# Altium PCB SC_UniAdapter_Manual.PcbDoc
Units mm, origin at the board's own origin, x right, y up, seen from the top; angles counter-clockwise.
Board outline 69.5 x 43.5 mm, 2 copper layers (Top Layer, Bottom Layer); 6 components, 60 nets, 150 pads, 27 vias.
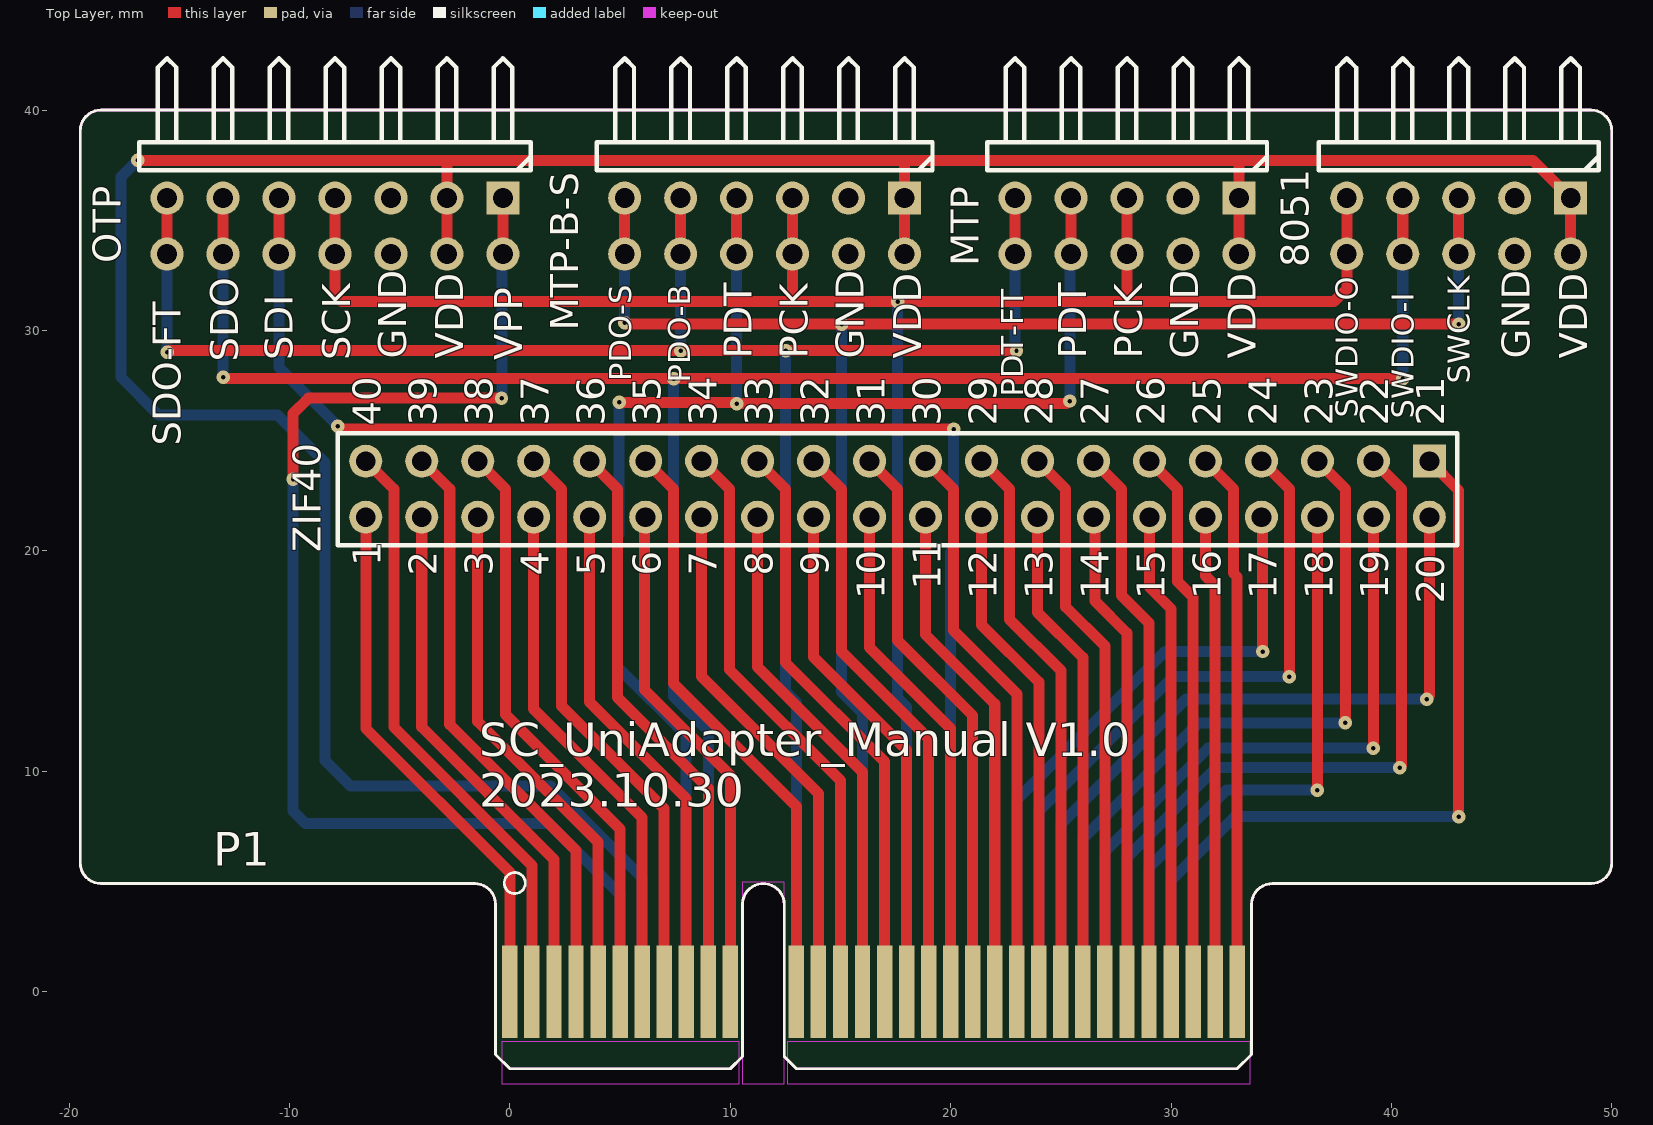
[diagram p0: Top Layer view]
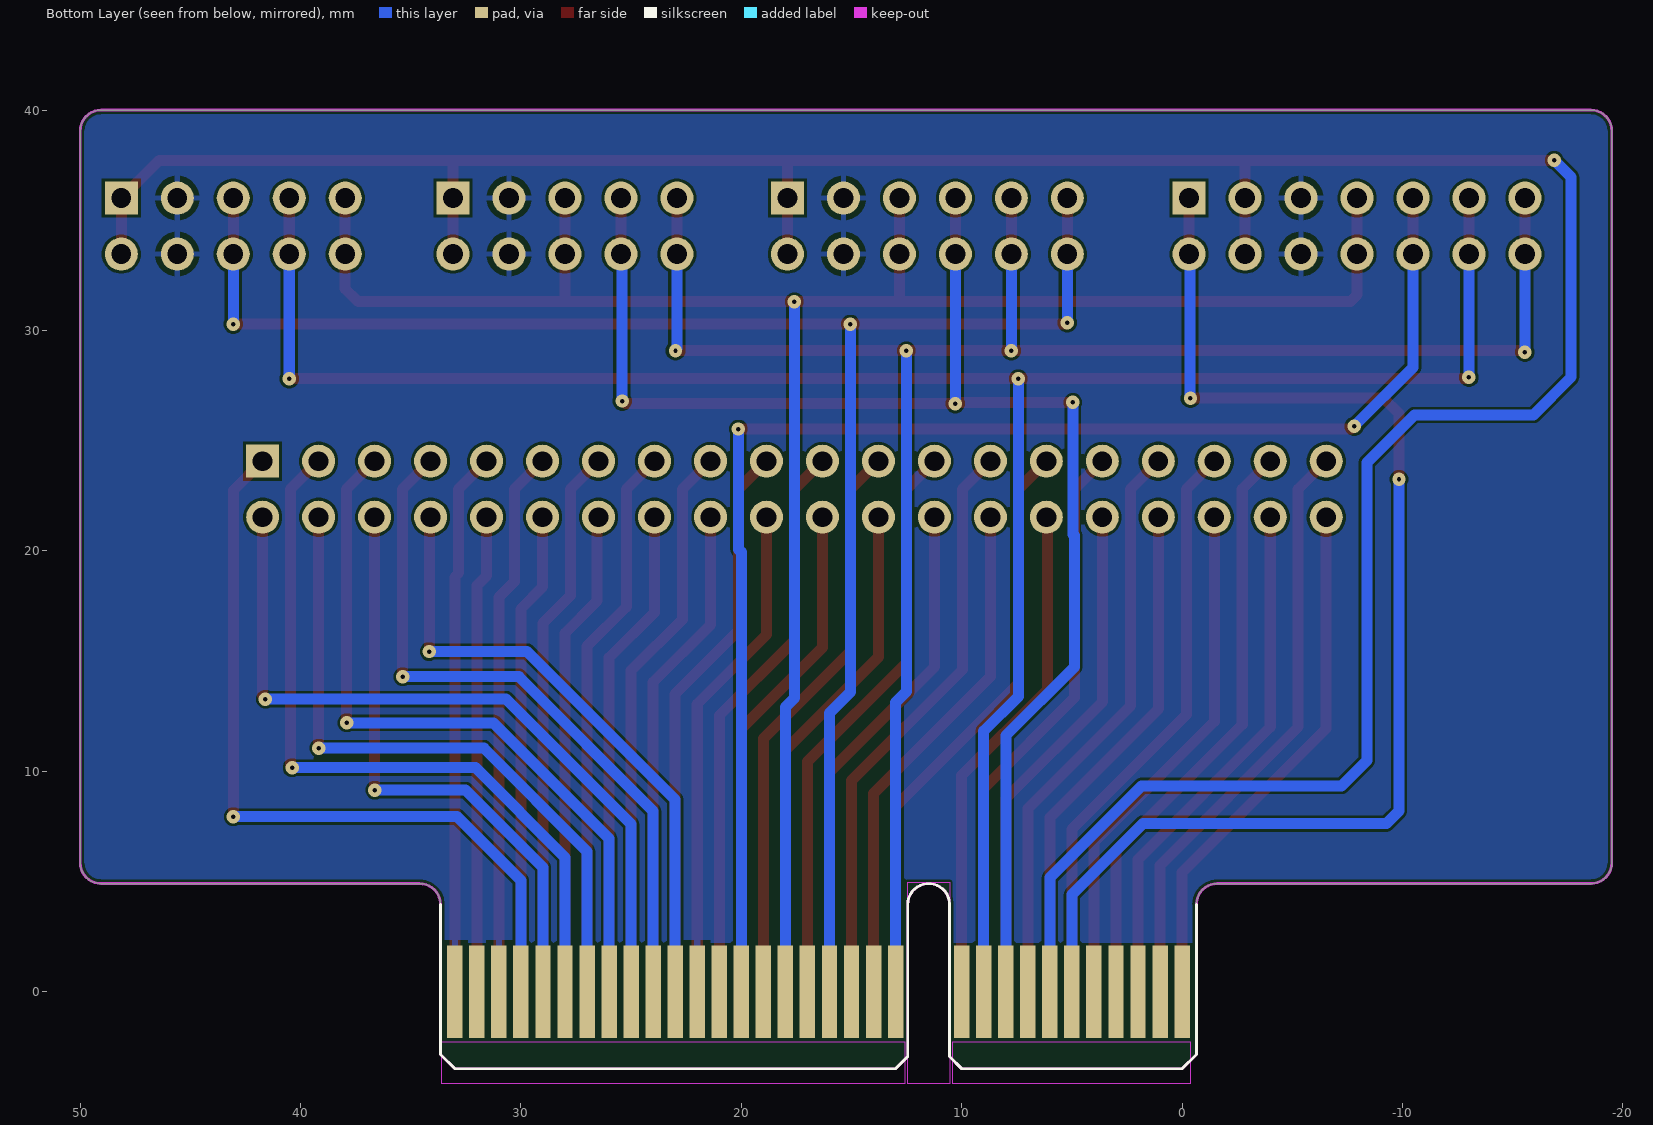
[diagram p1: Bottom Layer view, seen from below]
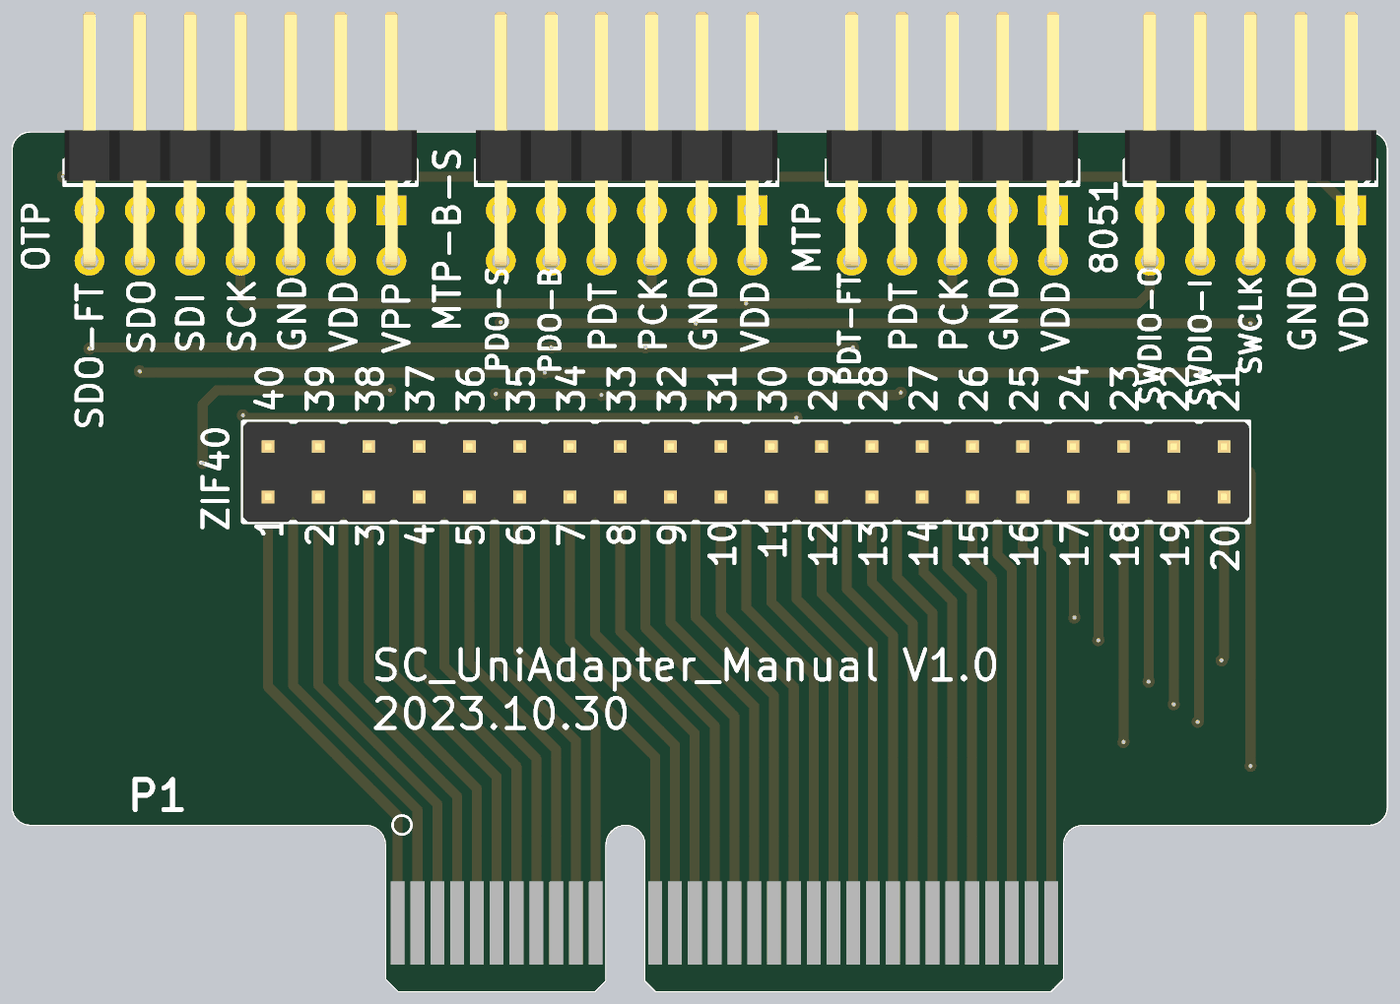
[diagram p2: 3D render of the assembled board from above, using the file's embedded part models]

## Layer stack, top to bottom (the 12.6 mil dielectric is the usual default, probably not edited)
Top Solder: solder mask 0.0102, Solder Resist, Dk 3.5
Top Layer: signal copper 0.0356
Dielectric1: dielectric 0.32, FR-4, Dk 4.8
Bottom Layer: signal copper 0.0356
Bottom Solder: solder mask 0.0102, Solder Resist, Dk 3.5

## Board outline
-0.65,-2.85 -0.65,3.955 ccw(c-1.598,3.952) -1.6,4.9 -18.55,4.9 cw(c-18.55,5.85) -19.5,5.85 -19.5,39.05 cw(c-18.55,39.05) -18.55,40 49.05,40 cw(c49.05,39.05) 50,39.05 50,5.85 cw(c49.05,5.85) 49.05,4.9 34.6,4.9 ccw(c34.6,3.95) 33.65,3.95 33.65,-2.85 33,-3.5 13,-3.5 12.45,-2.95 12.45,3.95 ccw(c11.5,3.95) 10.55,3.95 10.55,-2.95 10,-3.5 0,-3.5

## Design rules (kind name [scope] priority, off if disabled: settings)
Clearance [All] p1: gap=0.127 ignorepadtopadclearanceinfootprint=FALSE
FabricationTestpoint [(IsPad And (OnTopLayer Or OnBottomLayer))] p1: side=3 testpointundercomponent=TRUE minsize=1.016 maxsize=2.54 preferedsize=1.524 minholesize=0 maxholesize=1.016 preferedholesize=0.813 testpointgrid=0.025 allowsidetop=TRUE allowsidebottom=TRUE usegrid=TRUE gridtolerance=0
HoleToHoleClearance [All] p1: gap=0 allowstackedmicrovias=TRUE
MinimumSolderMaskSliver [All] p1: minsoldermaskwidth=0.01
PolygonConnect [All] p1: connectstyle=Relief reliefconductorwidth=0.254 reliefentries=4 polygonreliefangle="90 Angle" airgapwidth=0.254
RoutingVias [All] p1: holewidth=0.203 width=0.61 viastyle="Through Hole" minholewidth=0.203 minwidth=0.61 maxholewidth=0.711 maxwidth=1.27
SilkToSilkClearance [All] p1: silktosilkclearance=0
SilkToSolderMaskClearance [IsPad] p1: minsilkscreentomaskgap=0.01 clearancetoexposedcopper=TRUE
SolderMaskExpansion [IsVia] p1: expansion=0.102 istentingtop=TRUE
Width [All] p1: maxlimit=1 minlimit=0.254 preferedwidth=0.5
25 further rules are at their usual default settings.

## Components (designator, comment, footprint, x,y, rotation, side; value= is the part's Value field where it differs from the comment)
8051 "8051" HDR2X5H 48.133,36.005 r180 top (schematic designator P6)
MTP "MTP" HDR2X5H 33.084,36.005 r180 top (schematic designator P5)
MTP-B-S "MTP_BUSY_SUPPER" HDR2X6H 17.907,36.005 r180 top (schematic designator P4)
OTP "OTP" HDR2X7H -0.318,36.005 r180 top (schematic designator P3)
P1 "PCIE-E-64PIN-GoldfingerPlugboard" PCIE-E-64-GOLDFINGERPLUG 0,0 r0 top
ZIF40 "ZIF40" HDR2X20 41.719,24.066 r180 top (schematic designator P2)

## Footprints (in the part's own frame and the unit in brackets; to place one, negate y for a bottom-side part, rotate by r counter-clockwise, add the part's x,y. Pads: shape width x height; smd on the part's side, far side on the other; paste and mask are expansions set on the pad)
HDR2X5H [mm] "Connector; Header; 5x2 Position; Right Angle"
  rect 1.5x1.5 hole 0.9: 1(0,0)
  round 1.5 hole 0.9: 2(0,2.54) 3(2.54,0) 4(2.54,2.54) 5(5.08,0) 6(5.08,2.54) 7(7.62,0) 8(7.62,2.54) 9(10.16,0) 10(10.16,2.54)
  silkscreen extent -1.27,-6.35 11.43,-1.27, body extent -1.27,-10.04 11.43,2.86, height 5.08
HDR2X6H [mm] "Connector; Header; 6x2 Position; Right Angle"
  rect 1.5x1.5 hole 0.9: 1(0,0)
  round 1.5 hole 0.9: 2(0,2.54) 3(2.54,0) 4(2.54,2.54) 5(5.08,0) 6(5.08,2.54) 7(7.62,0) 8(7.62,2.54) 9(10.16,0) 10(10.16,2.54) 11(12.7,0) 12(12.7,2.54)
  silkscreen extent -1.27,-6.35 13.97,-1.27, body extent -1.27,-10.04 13.97,2.86, height 5.08
HDR2X7H [mm] "Connector; Header; 7x2 Position; Right Angle"
  rect 1.5x1.5 hole 0.9: 1(0,0)
  round 1.5 hole 0.9: 2(0,2.54) 3(2.54,0) 4(2.54,2.54) 5(5.08,0) 6(5.08,2.54) 7(7.62,0) 8(7.62,2.54) 9(10.16,0) 10(10.16,2.54) 11(12.7,0) 12(12.7,2.54) 13(15.24,0) 14(15.24,2.54)
  silkscreen extent -1.27,-6.35 16.51,-1.27, body extent -1.27,-10.04 16.51,2.86, height 5.08
HDR2X20 [mm] "Connector; Header; 20x2 Position"
  rect 1.5x1.5 hole 0.9: 1(0,0)
  round 1.5 hole 0.9: 2(0,2.54) 3(2.54,0) 4(2.54,2.54) 5(5.08,0) 6(5.08,2.54) 7(7.62,0) 8(7.62,2.54) 9(10.16,0) 10(10.16,2.54) 11(12.7,0) 12(12.7,2.54) 13(15.24,0) 14(15.24,2.54) 15(17.78,0) 16(17.78,2.54) 17(20.32,0) 18(20.32,2.54) 19(22.86,0) 20(22.86,2.54) 21(25.4,0) 22(25.4,2.54) 23(27.94,0) 24(27.94,2.54) 25(30.48,0) 26(30.48,2.54) 27(33.02,0) 28(33.02,2.54) 29(35.56,0) 30(35.56,2.54) 31(38.1,0) 32(38.1,2.54) 33(40.64,0) 34(40.64,2.54) 35(43.18,0) 36(43.18,2.54) 37(45.72,0) 38(45.72,2.54) 39(48.26,0) 40(48.26,2.54)
  silkscreen extent -1.27,-1.27 49.53,3.81, body extent -1.27,-1.27 49.53,3.81, height 8.54
PCIE-E-64-GOLDFINGERPLUG [mm] "64pin插槽金手指插板封装"
  rect 0.7x4.2 smd far side: A1(0,0) A2(1,0) A3(2,0) A4(3,0) A5(4,0) A6(5,0) A7(6,0) A8(7,0) A9(8,0) A10(9,0) A11(10,0) A12(13,0) A13(14,0) A14(15,0) A15(16,0) A16(17,0) A17(18,0) A18(19,0) A19(20,0) A20(21,0) A21(22,0) A22(23,0) A23(24,0) A24(25,0) A25(26,0) A26(27,0) A27(28,0) A28(29,0) A29(30,0) A30(31,0) A31(32,0) A32(33,0)
  rect 0.7x4.2 smd: B1(0,0) B2(1,0) B3(2,0) B4(3,0) B5(4,0) B6(5,0) B7(6,0) B8(7,0) B9(8,0) B10(9,0) B11(10,0) B12(13,0) B13(14,0) B14(15,0) B15(16,0) B16(17,0) B17(18,0) B18(19,0) B19(20,0) B20(21,0) B21(22,0) B22(23,0) B23(24,0) B24(25,0) B25(26,0) B26(27,0) B27(28,0) B28(29,0) B29(30,0) B30(31,0) B31(32,0) B32(33,0)
  Top Layer keep-out region: 12.573,-4.191 33.592,-4.191 33.592,-2.286 12.573,-2.286
  Top Layer keep-out region: 10.541,-4.191 12.446,-4.191 12.446,4.953 10.541,4.953
  Top Layer keep-out region: -0.381,-4.191 10.414,-4.191 10.414,-2.286 -0.381,-2.286
  Bottom Layer keep-out region: 12.573,-4.191 33.592,-4.191 33.592,-2.286 12.573,-2.286
  Bottom Layer keep-out region: 10.541,-4.191 12.446,-4.191 12.446,4.953 10.541,4.953
  Bottom Layer keep-out region: -0.381,-4.191 10.414,-4.191 10.414,-2.286 -0.381,-2.286
  silkscreen extent -0.65,-3.5 33.65,5.4

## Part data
8051 MTP: library part "Header 5X2H", "Header, 5-Pin, Dual row, Right Angle"
MTP-B-S: library part "Header 6X2H", "Header, 6-Pin, Dual row, Right Angle"
OTP: library part "Header 7X2H", "Header, 7-Pin, Dual row, Right Angle"
P1: library part CMP-002-000020-2, "PCIE-E 64脚 金手指插板"
ZIF40: library part "Header 20X2", "Header, 20-Pin, Dual row"

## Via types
v1: diameter 0.61, hole 0.203, Top Layer to Bottom Layer, tented both sides, 27 vias

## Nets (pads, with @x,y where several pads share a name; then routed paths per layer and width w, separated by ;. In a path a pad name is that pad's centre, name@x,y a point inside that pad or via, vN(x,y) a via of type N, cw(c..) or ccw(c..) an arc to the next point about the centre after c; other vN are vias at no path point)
8051-SWCLK-PO11: 8051.5 8051.6 MTP-B-S.11 MTP-B-S.12 P1.A15 | length 79.9
  Top Layer w0.5: v1(5.207,30.353) 5.237,30.353 5.3,30.29 v1(15.05,30.29) v1(43.053,30.29) ; MTP-B-S.12 MTP-B-S.11 ; 8051.6 8051.5
  Bottom Layer w0.5: v1(5.207,30.353) MTP-B-S.12 ; v1(15.05,30.29) 15.05,13.592 16,12.642 P1.A15 ; v1(43.053,30.29) 8051.6
8051-SWDIO-I-PIN4: 8051.7 8051.8 OTP.11 OTP.12 P1.A10 | length 98.3
  Top Layer w0.5: v1(-13.018,27.877) -12.988,27.877 -12.924,27.813 v1(7.429,27.813) v1(40.513,27.813) ; OTP.12 OTP.11 ; 8051.8 8051.7
  Bottom Layer w0.5: v1(-13.018,27.877) OTP.12 ; v1(7.429,27.813) 7.429,13.394 9,11.824 P1.A10 ; v1(40.513,27.813) 8051.8
8051-SWDIO-O-PO7: 8051.9 8051.10 MTP-B-S.5 MTP-B-S.6 MTP.5 MTP.6 OTP.7 OTP.8 P1.A17 | length 95.8
  Top Layer w0.5: OTP.7 OTP.8 -7.938,31.598 -7.645,31.305 12.89,31.305 ; MTP-B-S.5 MTP-B-S.6 12.827,31.369 12.89,31.305 ; MTP.5 MTP.6 28.003,31.432 27.877,31.305 ; 8051.9 8051.10 37.973,31.877 37.401,31.305 27.877,31.305 ; 12.89,31.305 v1(17.59,31.305) 27.877,31.305
  Bottom Layer w0.5: v1(17.59,31.305) 17.59,13.322 18,12.912 P1.A17
DIP1: P1.B1 ZIF40.40 | length 24.2
  Top Layer w0.5: ZIF40.40 -6.54,11.938 0,5.397 P1.B1
DIP2: P1.B3 ZIF40.38 | length 24
  Top Layer w0.5: ZIF40.38 -4,12.002 2,6.001 P1.B3
DIP3: P1.B5 ZIF40.36 | length 23.8
  Top Layer w0.5: ZIF40.36 -1.46,12.255 4,6.795 P1.B5
DIP4: P1.B7 ZIF40.34 | length 23.6
  Top Layer w0.5: ZIF40.34 1.079,12.827 6,7.907 P1.B7
DIP5: P1.B9 ZIF40.32 | length 23.3
  Top Layer w0.5: ZIF40.32 3.619,13.144 8,8.764 P1.B9
DIP6: P1.B11 ZIF40.30 | length 23.2
  Top Layer w0.5: ZIF40.30 6.096,21.463 6.096,13.716 10,9.812 P1.B11
DIP7: P1.B13 ZIF40.28 | length 23.7
  Top Layer w0.5: ZIF40.28 8.7,14.287 14,8.987 P1.B13
DIP8: P1.B15 ZIF40.26 | length 23.5
  Top Layer w0.5: ZIF40.26 11.239,14.732 16,9.972 P1.B15
DIP9: P1.B17 ZIF40.24 | length 23.3
  Top Layer w0.5: ZIF40.24 13.779,15.176 18,10.956 P1.B17
DIP10: P1.B19 ZIF40.22 | length 23.1
  Top Layer w0.5: ZIF40.22 16.319,15.621 20,11.94 P1.B19
DIP11: P1.B21 ZIF40.20 | length 22.8
  Top Layer w0.5: ZIF40.20 18.86,16.192 22,13.052 P1.B21
DIP12: P1.B23 ZIF40.18 | length 22.6
  Top Layer w0.5: ZIF40.18 21.399,16.637 24,14.036 P1.B23
DIP13: P1.B25 ZIF40.16 | length 22.4
  Top Layer w0.5: ZIF40.16 23.939,17.209 26,15.148 P1.B25
DIP14: P1.B27 ZIF40.14 | length 22.2
  Top Layer w0.5: ZIF40.14 26.543,21.463 26.543,17.716 28,16.26 P1.B27
DIP15: P1.B29 ZIF40.12 | length 21.9
  Top Layer w0.5: ZIF40.12 29.019,18.351 30,17.371 P1.B29
DIP16: P1.B31 ZIF40.10 | length 21.7
  Top Layer w0.5: ZIF40.10 31.559,18.86 32,18.419 P1.B31
DIP17: P1.A22 ZIF40.8 | length 28.8
  Top Layer w0.5: ZIF40.8 34.142,21.484 34.142,15.451 v1(34.163,15.43)
  Bottom Layer w0.5: P1.A22 23,8.713 29.718,15.43 v1(34.163,15.43)
DIP18: P1.A28 ZIF40.6 | length 27.1
  Top Layer w0.5: v1(36.639,9.144) ZIF40.6
  Bottom Layer w0.5: P1.A28 29,5.632 32.512,9.144 v1(36.639,9.144)
DIP19: P1.A26 ZIF40.4 | length 31
  Top Layer w0.5: v1(39.179,11.049) ZIF40.4
  Bottom Layer w0.5: P1.A26 27,6.362 31.686,11.049 v1(39.179,11.049)
DIP20: P1.A24 ZIF40.2 | length 34.8
  Top Layer w0.5: v1(41.593,13.271) 41.593,13.301 41.719,13.428 ZIF40.2
  Bottom Layer w0.5: P1.A24 25,7.601 30.67,13.271 v1(41.593,13.271)
DIP21: P1.A29 ZIF40.1 | length 36
  Top Layer w0.5: ZIF40.1 43.053,22.733 v1(43.053,7.938)
  Bottom Layer w0.5: P1.A29 30,5.044 32.893,7.938 v1(43.053,7.938)
DIP22: P1.A27 ZIF40.3 | length 34.6
  Top Layer w0.5: ZIF40.3 40.45,22.796 40.45,10.253 40.386,10.19 v1(40.386,10.16)
  Bottom Layer w0.5: P1.A27 28,6.092 32.067,10.16 v1(40.386,10.16)
DIP23: P1.A25 ZIF40.5 | length 33.4
  Top Layer w0.5: ZIF40.5 37.91,22.796 v1(37.91,12.192)
  Bottom Layer w0.5: P1.A25 26,6.95 31.242,12.192 v1(37.91,12.192)
DIP24: P1.A23 ZIF40.7 | length 32.4
  Top Layer w0.5: ZIF40.7 35.369,22.796 v1(35.369,14.287)
  Bottom Layer w0.5: P1.A23 24,8.189 30.099,14.287 v1(35.369,14.287)
DIP25: P1.B32 ZIF40.9 | length 24.7
  Top Layer w0.5: ZIF40.9 32.829,22.796 32.829,18.986 33,18.816 P1.B32
DIP26: P1.B30 ZIF40.11 | length 24.9
  Top Layer w0.5: ZIF40.11 30.29,22.796 30.29,18.605 31,17.895 P1.B30
DIP27: P1.B28 ZIF40.13 | length 25.1
  Top Layer w0.5: ZIF40.13 27.749,22.796 27.749,17.97 29,16.72 P1.B28
DIP28: P1.B26 ZIF40.15 | length 25.3
  Top Layer w0.5: ZIF40.15 25.209,22.796 25.209,17.462 27,15.672 P1.B26
DIP29: P1.B24 ZIF40.17 | length 25.6
  Top Layer w0.5: ZIF40.17 22.669,22.796 22.669,16.891 25,14.56 P1.B24
DIP30: P1.B22 ZIF40.19 | length 25.8
  Top Layer w0.5: ZIF40.19 20.13,22.796 20.13,16.383 23,13.512 P1.B22
DIP31: P1.B20 ZIF40.21 | length 26
  Top Layer w0.5: ZIF40.21 17.59,22.796 17.59,15.938 21,12.528 P1.B20
DIP32: P1.B18 ZIF40.23 | length 26.2
  Top Layer w0.5: ZIF40.23 15.05,22.796 15.05,15.43 19,11.48 P1.B18
DIP33: P1.B16 ZIF40.25 | length 26.5
  Top Layer w0.5: ZIF40.25 12.509,22.796 12.509,14.922 17,10.432 P1.B16
DIP34: P1.B14 ZIF40.27 | length 26.7
  Top Layer w0.5: ZIF40.27 9.97,22.796 9.97,14.605 15,9.575 P1.B14
DIP35: P1.B12 ZIF40.29 | length 26.9
  Top Layer w0.5: ZIF40.29 7.429,22.796 7.429,13.97 13,8.4 P1.B12
DIP36: P1.B10 ZIF40.31 | length 26.3
  Top Layer w0.5: ZIF40.31 4.889,22.796 4.889,13.335 9,9.225 P1.B10
DIP37: P1.B8 ZIF40.33 | length 26.5
  Top Layer w0.5: ZIF40.33 2.349,22.796 2.349,12.954 7,8.304 P1.B8
DIP38: P1.B6 ZIF40.35 | length 26.7
  Top Layer w0.5: ZIF40.35 -0.191,22.796 -0.191,12.573 5,7.383 P1.B6
DIP39: P1.B4 ZIF40.37 | length 27
  Top Layer w0.5: ZIF40.37 -2.73,22.796 -2.73,12.128 3,6.398 P1.B4
DIP40: P1.B2 ZIF40.39 | length 27.2
  Top Layer w0.5: ZIF40.39 -5.271,22.796 -5.271,12.002 1,5.731 P1.B2
FT_PIN0: MTP-B-S.9 MTP-B-S.10 MTP.9 MTP.10 OTP.13 OTP.14 P1.A12 | length 88.7
  Top Layer w0.5: v1(-15.557,29.019) -15.528,29.019 -15.464,29.083 v1(7.747,29.083) v1(12.509,29.083) v1(22.987,29.083) ; OTP.14 OTP.13 ; MTP-B-S.10 MTP-B-S.9 ; MTP.10 MTP.9
  Bottom Layer w0.5: v1(-15.557,29.019) OTP.14 ; v1(7.747,29.083) MTP-B-S.10 ; v1(12.509,29.083) 12.509,24.892 12.509,13.616 13,13.126 P1.A12 ; MTP.10 22.924,29.176 22.987,29.113 v1(22.987,29.083)
GND: 8051.3 8051.4 MTP-B-S.3 MTP-B-S.4 MTP.3 MTP.4 OTP.5 OTP.6 P1.A21 P1.A30 P1.A32
MTP-PDT-PO5: MTP-B-S.7 MTP-B-S.8 MTP.7 MTP.8 P1.A9 | length 67.1
  Top Layer w0.5: v1(4.953,26.733) 10.204,26.733 10.258,26.68 25.254,26.68 25.37,26.797 v1(25.4,26.797) ; MTP-B-S.8 MTP-B-S.7 ; MTP.8 MTP.7
  Bottom Layer w0.5: v1(4.953,26.733) 4.953,20.752 4.889,20.688 4.889,14.736 8,11.625 P1.A9 ; v1@10.287,26.681 MTP-B-S.8@10.287,33.464 ; v1(25.4,26.797) 25.421,26.818 25.421,33.422 MTP.8
  other v1: 10.287,26.68
OTP-SDI-PO6: OTP.9 OTP.10 P1.A19 | length 65
  Top Layer w0.5: OTP.10 OTP.9 ; v1(-7.81,25.654) -7.781,25.654 -7.654,25.527 v1(20.13,25.527)
  Bottom Layer w0.5: OTP.10 -10.477,28.321 v1(-7.81,25.654) ; P1.A19 20,19.937 20.13,20.066 v1(20.13,25.527)
PD1_RST: P1.A14
PIN1: P1.A18
PIN2: P1.A16
PO3: P1.A13
PO4: P1.A11
V5_D1: P1.A2
V5_D2: P1.A4
V33_D1: P1.A1
V33_D2: P1.A3
VDD: 8051.1 8051.2 MTP-B-S.1 MTP-B-S.2 MTP.1 MTP.2 OTP.3 OTP.4 P1.A7 | length 137.4
  Top Layer w0.5: v1(-16.891,37.719) -2.857,37.719 ; OTP.4 OTP.3 -2.857,37.719 ; MTP-B-S.2 MTP-B-S.1 17.907,37.719 ; MTP.2 MTP.1 33.084,37.655 33.147,37.719 ; 8051.2 8051.1 46.419,37.719 33.147,37.719 ; -2.857,37.719 17.907,37.719 ; 17.907,37.719 33.147,37.719
  Bottom Layer w0.5: v1(-16.891,37.719) -17.653,36.957 -17.653,27.877 -15.938,26.162 -10.541,26.162 -8.382,24.003 -8.382,10.477 -7.239,9.335 1.841,9.335 6,5.176 P1.A7
VDD1: P1.A5
VPP: OTP.1 OTP.2 P1.A6 | length 57.7
  Top Layer w0.5: v1(-9.842,23.241) -9.842,26.226 -9.144,26.924 v1(-0.381,26.924) ; OTP.2 OTP.1
  Bottom Layer w0.5: v1(-9.842,23.241) -9.842,8.191 -9.271,7.62 1.778,7.62 5,4.398 P1.A6 ; v1(-0.381,26.924) -0.36,26.945 -0.36,33.422 OTP.2
VPP2: P1.A8
pads on no net: P1.A20 P1.A31

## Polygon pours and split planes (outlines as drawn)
GND on Bottom Layer "GND_L02_P000" (solid, remove dead copper, pour order 0): 50.038,40.008 50.038,37.973 50.038,5.651 49.911,5.524 49.911,5.397 49.721,5.207 49.721,5.143 49.657,5.143 49.466,4.953 49.149,4.953 49.085,4.889 34.29,4.889 34.163,4.763 34.036,4.763 33.846,4.572 33.846,4.508 33.718,4.381 33.718,4.255 33.655,4.191 33.655,-2.857 33.02,-3.492 13.018,-3.492 12.446,-2.921 12.446,4.318 11.938,4.826 11.747,4.826 11.684,4.889 11.303,4.889 11.239,4.826 11.049,4.826 10.668,4.445 10.668,4.318 10.604,4.255 10.604,4.127 10.541,4.064 10.541,-2.921 9.97,-3.492 0,-3.492 -0.699,-2.794 -0.699,4.318 -1.206,4.826 -1.397,4.826 -1.46,4.889 -18.86,4.889 -19.113,5.143 -19.177,5.143 -19.367,5.334 -19.367,5.461 -19.558,5.651 -19.558,38.481 -19.558,38.544 -19.558,38.862 -19.558,39.306 -19.558,40.008

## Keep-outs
Keep-Out Layer:
  the board outline again, w0.127

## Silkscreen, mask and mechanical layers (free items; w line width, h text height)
Top Overlay:
  the board outline again, w0.127
  text "GND" at -4.712,28.715 h1.27 r90
  text "VDD" at -2.108,28.715 h1.27 r90
  text "PDT" at 10.973,28.715 h1.27 r90
  text "PCK" at 13.513,28.715 h1.27 r90
  text "GND" at 16.053,28.715 h1.27 r90
  text "VDD" at 18.656,28.715 h1.27 r90
  text "PDT" at 26.149,28.715 h1.27 r90
  text "PCK" at 28.689,28.715 h1.27 r90
  text "GND" at 31.229,28.715 h1.27 r90
  text "VDD" at 33.833,28.715 h1.27 r90
  text "GND" at 46.279,28.715 h1.27 r90
  text "VDD" at 48.882,28.715 h1.27 r90
  text "SDI" at -9.855,28.651 h1.27 r90
  text "SCK" at -7.252,28.651 h1.27 r90
  text "VPP" at 0.559,28.651 h1.27 r90
  text "SDO" at -12.332,28.588 h1.27 r90
  text "PDO-S" at 5.512,27.699 h1.02 r90
  text "PDO-B" at 8.179,27.635 h1.02 r90
  text "SWCLK" at 43.548,27.572 h1.02 r90
  text "PDT-FT" at 23.292,27 h1.02 r90
  text "SWDIO-O" at 38.468,26.048 h1.02 r90
  text "SWDIO-I" at 41.008,25.984 h1.02 r90
  text "40" at -5.855,25.667 h1.27 r90
  text "39" at -3.315,25.667 h1.27 r90
  text "38" at -0.775,25.667 h1.27 r90
  text "37" at 1.765,25.667 h1.27 r90
  text "36" at 4.305,25.667 h1.27 r90
  text "35" at 6.845,25.667 h1.27 r90
  text "34" at 9.385,25.667 h1.27 r90
  text "33" at 11.925,25.667 h1.27 r90
  text "32" at 14.465,25.667 h1.27 r90
  text "31" at 17.005,25.667 h1.27 r90
  text "30" at 19.545,25.667 h1.27 r90
  text "29" at 22.085,25.667 h1.27 r90
  text "28" at 24.625,25.667 h1.27 r90
  text "27" at 27.165,25.667 h1.27 r90
  text "26" at 29.705,25.667 h1.27 r90
  text "25" at 32.245,25.667 h1.27 r90
  text "24" at 34.785,25.667 h1.27 r90
  text "23" at 37.325,25.667 h1.27 r90
  text "22" at 39.865,25.667 h1.27 r90
  text "21" at 42.405,25.667 h1.27 r90
  text "SDO-FT" at -14.935,24.778 h1.27 r90
  text "1" at -5.855,19.295 h1.27 r90
  text "2" at -3.315,18.872 h1.27 r90
  text "3" at -0.775,18.872 h1.27 r90
  text "4" at 1.765,18.872 h1.27 r90
  text "5" at 4.305,18.872 h1.27 r90
  text "6" at 6.845,18.872 h1.27 r90
  text "7" at 9.385,18.872 h1.27 r90
  text "8" at 11.925,18.872 h1.27 r90
  text "9" at 14.465,18.872 h1.27 r90
  text "11" at 19.545,18.237 h1.27 r90
  text "10" at 17.005,17.814 h1.27 r90
  text "12" at 22.085,17.814 h1.27 r90
  text "13" at 24.625,17.814 h1.27 r90
  text "14" at 27.165,17.814 h1.27 r90
  text "15" at 29.705,17.814 h1.27 r90
  text "16" at 32.245,17.814 h1.27 r90
  text "17" at 34.785,17.814 h1.27 r90
  text "18" at 37.325,17.814 h1.27 r90
  text "19" at 39.865,17.814 h1.27 r90
  text "20" at 42.405,17.602 h1.27 r90
  text "SC_UniAdapter_Manual V1.0 / 2023.10.30" at -1.397,8.382 h1.52
Mechanical 1:
  the board outline again, w0.127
